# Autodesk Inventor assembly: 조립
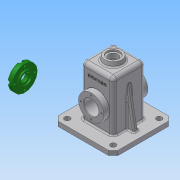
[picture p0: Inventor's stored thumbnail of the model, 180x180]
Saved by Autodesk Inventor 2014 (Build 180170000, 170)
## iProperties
Created: 2016-02
Part Number: 조립
Document SubType Name: Assembly
Designer: User
Author: User
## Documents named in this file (3)
- C:\Documents and Settings\User\My Documents\Inventor\460211V1024\조립.iam
- C:\Documents and Settings\User\My Documents\Inventor\460211V1024\본체.ipt
- C:\Documents and Settings\User\My Documents\Inventor\460211V1024\앞커버.ipt
